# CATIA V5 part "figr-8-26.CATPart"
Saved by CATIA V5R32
Part number: Part3
Bounding box of the stored display mesh (mm): x -50 to 50, y -40 to 40, z 0 to 36
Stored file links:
  D:\PROJECTS\Project 2022\CATIA V5 6R 2022\Resources\Part Files\c08_catia_v5_6r2022_prt\figr-8-26.CATPart
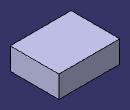
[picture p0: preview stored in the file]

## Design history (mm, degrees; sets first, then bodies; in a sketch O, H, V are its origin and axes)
Body1 (main body)
  Sketch1 on xy-plane, origin (0, 0, 0), H (1, 0, 0), V (0, 1, 0)
    line L1 (-50, 40) -> (50, 40)
    line L2 (50, 40) -> (50, -40)
    line L3 (50, -40) -> (-50, -40)
    line L4 (-50, -40) -> (-50, 40)
    horizontal: L1 H, L3 H
    vertical: L2 V, L4 V
  Pad1: profile Sketch1, direction (0, 0, 1), length 36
